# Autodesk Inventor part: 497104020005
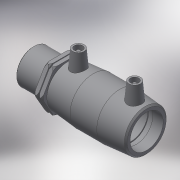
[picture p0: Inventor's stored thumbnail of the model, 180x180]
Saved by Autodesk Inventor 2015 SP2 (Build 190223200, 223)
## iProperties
Created: 2017-06
Part Number: 497104020005
Material: Generic
Description: PLASSON PE MALE TRANSITION COUPLER 20-1/2"
Document SubType Name: Modeling
Designer: KIM
Mass: 55.0731 g
Surface Area: 148.067 cm^2
Volume: 55.0731 cm^3
Density: 1 g/cm^3
Appearance: Default
Author: KIM
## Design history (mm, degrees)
derived "497104.ipt"
feature "Solid1::497104.ipt"
tag "TaggingFeature1"
body "Solid1"
other parameters: "d0" = 76, "d2" = 31, "d3" = 37, "d4" = 25.33333, "d5" = 27.9, "d6" = 19, "d8" = 168 deg, "d10" = 14.8, "d11" = 4.93333, "d29" = 34, "d30" = 14, "d31" = 26.6, "d34" = 5 deg, "d41" = 4, "d42" = 14, "d43" = 0, "d48" = 3, "d49" = 0, "d57" = 14, "d58" = 20.955, "d59" = 16.764, "d60" = 18.9, "d61" = 29.337, "d62" = 0.4191, "d65" = 0.93, "d70" = 0.1, "d71" = 21, "d72" = 5.25, "d73" = 14.8, "d75" = 0, "d76" = 0.525, "d77" = 2.3625, "d78" = 29.337, "L_" = 97, "L_2" = 37, "D_1" = 31, "A_" = 34, "d_2" = 12, "L_1" = 21, "D_" = 14, "R_" = 20.955
